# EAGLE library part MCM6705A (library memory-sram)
MEMORY
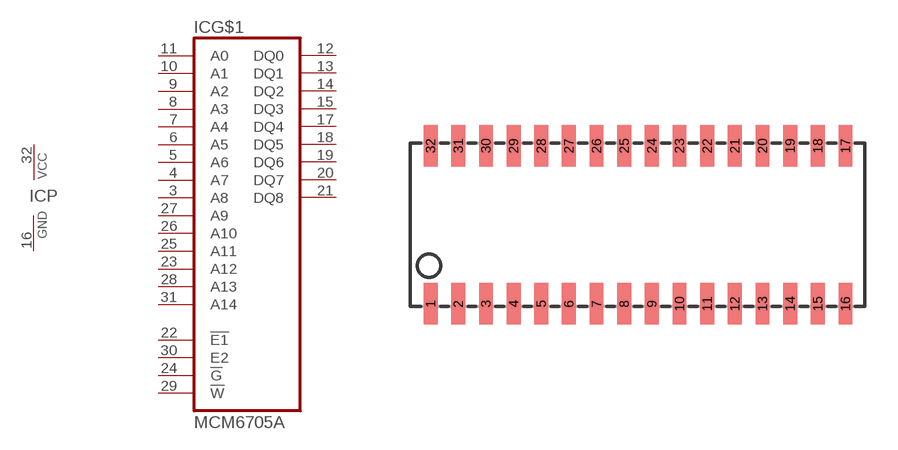
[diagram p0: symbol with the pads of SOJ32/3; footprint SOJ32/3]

Designator prefix IC; gates G$1=CM6705A P=PWRN

## MCM6705A  [SOJ32/3]
3  G$1:A8  in
4  G$1:A7  in
5  G$1:A6  in
6  G$1:A5  in
7  G$1:A4  in
8  G$1:A3  in
9  G$1:A2  in
10  G$1:A1  in
11  G$1:A0  in
12  G$1:DQ0
13  G$1:DQ1
14  G$1:DQ2
15  G$1:DQ3
16  P:GND  pwr
17  G$1:DQ4
18  G$1:DQ5
19  G$1:DQ6
20  G$1:DQ7
21  G$1:DQ8
22  G$1:!E1  in
23  G$1:A12  in
24  G$1:!G  in
25  G$1:A11  in
26  G$1:A10  in
27  G$1:A9  in
28  G$1:A13  in
29  G$1:!W  in
30  G$1:E2  in
31  G$1:A14  in
32  P:VCC  pwr

## Footprint SOJ32/3 (pad centres in mm)
Small Outline J-Bend
smd 0.635 x 1.905: 1 -9.525,-3.632; 2 -8.255,-3.632; 3 -6.985,-3.632; 4 -5.715,-3.632; 5 -4.445,-3.632; 6 -3.175,-3.632; 7 -1.905,-3.632; 8 -0.635,-3.632; 9 0.635,-3.632; 10 1.905,-3.632; 11 3.175,-3.632; 12 4.445,-3.632; 13 5.715,-3.632; 14 6.985,-3.632; 15 8.255,-3.632; 16 9.525,-3.632; 17 9.525,3.632; 18 8.255,3.632; 19 6.985,3.632; 20 5.715,3.632; 21 4.445,3.632; 22 3.175,3.632; 23 1.905,3.632; 24 0.635,3.632; 25 -0.635,3.632; 26 -1.905,3.632; 27 -3.175,3.632; 28 -4.445,3.632; 29 -5.715,3.632; 30 -6.985,3.632; 31 -8.255,3.632; 32 -9.525,3.632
